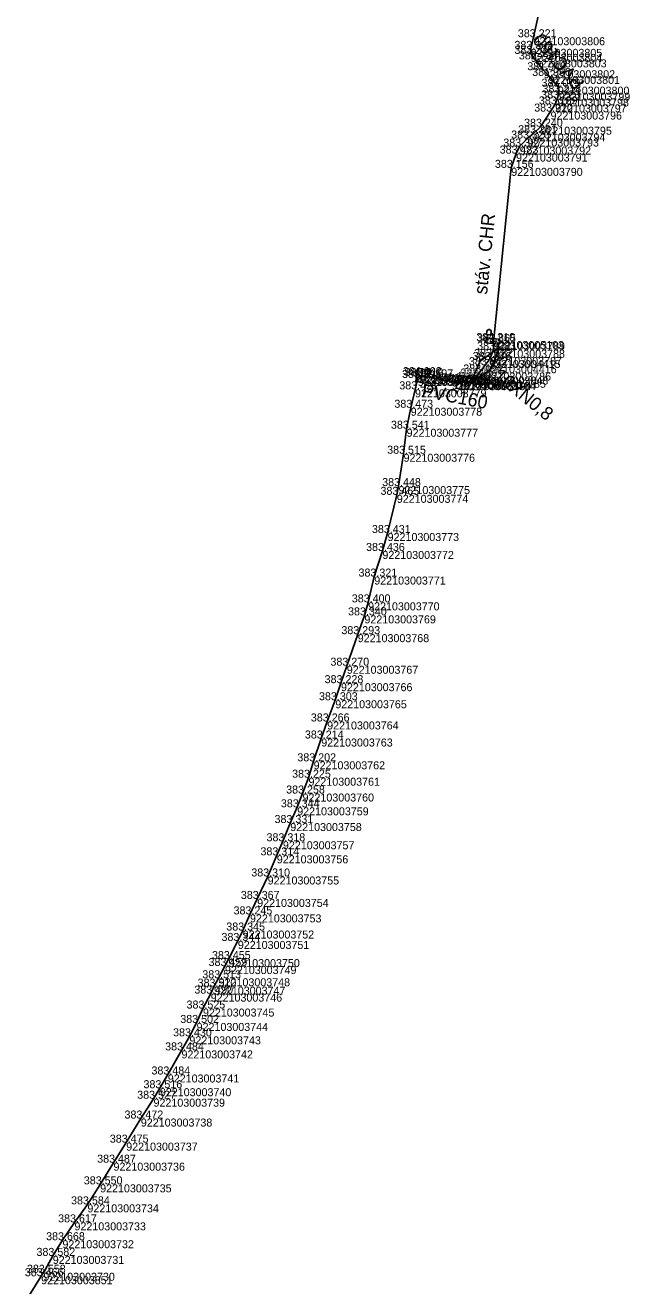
# Model space of a CAD drawing. Extents: x -771047 to -756200, y -1053876 to -1046520.
# Drawn here: x -756827.8 to -756737.2, y -1047067 to -1046877.9 of the extents above; entities that cross this region are included whole.
import ezdxf

# ---------------------------------------------------------------- set-up
doc = ezdxf.new("R2010")
doc.units = 0
for name, color, linetype in [('Vrstva 32', 7, 'Continuous'), ('Vrstva 33', 7, 'Continuous'), ('Vrstva 60', 7, 'Continuous'), ('Vrstva 61', 7, 'Continuous')]:
    doc.layers.add(name, color=color, linetype=linetype)

msp = doc.modelspace()

# ---------------------------------------------------------------- linework, layer by layer
at = {"layer": 'Vrstva 32'}
for points in [[(-756751.57, -1046879.71), (-756750.8, -1046876.1)], [(-756748.33, -1046889.77), (-756747.99, -1046888.89), (-756747.79, -1046888.02), (-756747.92, -1046887.12), (-756749.33, -1046885.51), (-756750.06, -1046884.66), (-756751.33, -1046883.03), (-756751.99, -1046882.2), (-756751.99, -1046881.45), (-756751.57, -1046879.71)], [(-756753.66, -1046896.11), (-756752.48, -1046894.9), (-756751.52, -1046894.11), (-756750.55, -1046893.13), (-756749.03, -1046890.86), (-756748.33, -1046889.77)], [(-756768.46, -1046930.51), (-756766.97, -1046930.72), (-756763.83, -1046931.32), (-756761.94, -1046931.43), (-756760.44, -1046931.08), (-756760.08, -1046930.6), (-756759.66, -1046929.99), (-756758.82, -1046928.9), (-756758.24, -1046928.11), (-756758.03, -1046927.68), (-756757.58, -1046926.58), (-756757.57, -1046925.42), (-756754.92, -1046899.3), (-756754.2, -1046897.16), (-756753.66, -1046896.11)], [(-756761.04, -1046931.61), (-756759.6, -1046928.27), (-756756.61, -1046926.19), (-756758.05, -1046929.53), (-756761.04, -1046931.61)], [(-756768.46, -1046930.51), (-756768.93, -1046930.81), (-756769.34, -1046932.52), (-756769.99, -1046935.28), (-756770.6, -1046938.43), (-756771.06, -1046942.18), (-756771.81, -1046947.03), (-756772.07, -1046948.34), (-756773.45, -1046954.07), (-756774.23, -1046956.76), (-756775.45, -1046960.6), (-756776.37, -1046964.47), (-756776.93, -1046966.42), (-756777.93, -1046969.24), (-756779.57, -1046973.97), (-756780.44, -1046976.59), (-756781.29, -1046979.15), (-756782.51, -1046982.33), (-756783.4, -1046984.89), (-756784.54, -1046988.31), (-756785.31, -1046990.77), (-756786.2, -1046993.14), (-756787, -1046995.21), (-756788.04, -1046997.57), (-756789.14, -1047000.3), (-756790.06, -1047002.41), (-756791.43, -1047005.58), (-756793, -1047008.95), (-756794.08, -1047011.27), (-756795.17, -1047013.69), (-756795.9, -1047015.25), (-756797.32, -1047017.97), (-756797.83, -1047019.02), (-756798.78, -1047020.85), (-756799.48, -1047022.11), (-756799.97, -1047023.15), (-756801.13, -1047025.39), (-756802.08, -1047027.55), (-756803.16, -1047029.56), (-756804.35, -1047031.67), (-756806.4, -1047035.28), (-756807.59, -1047037.34), (-756808.54, -1047038.92), (-756810.44, -1047041.89), (-756812.63, -1047045.5), (-756814.54, -1047048.51), (-756816.54, -1047051.76), (-756818.45, -1047054.76), (-756820.39, -1047057.46), (-756822.19, -1047060.14), (-756823.64, -1047062.49), (-756825.05, -1047065.02), (-756825.38, -1047065.54), (-756827.16, -1047068.41)]]:
    msp.add_lwpolyline(points, dxfattribs=at)
at = {"layer": 'Vrstva 33'}
for points in [[(-756748.33, -1046889.77), (-756747.99, -1046888.89), (-756747.79, -1046888.02), (-756747.92, -1046887.12), (-756749.33, -1046885.51), (-756750.06, -1046884.66), (-756751.33, -1046883.03), (-756751.99, -1046882.2), (-756751.99, -1046881.45), (-756751.57, -1046879.71)], [(-756757.57, -1046925.42), (-756754.92, -1046899.3), (-756754.2, -1046897.16), (-756753.66, -1046896.11)], [(-756758.62, -1046924.29), (-756758.56, -1046923.77)], [(-756757.37, -1046924.41), (-756758.62, -1046924.29)], [(-756758.56, -1046923.77), (-756758.5, -1046923.62), (-756758.28, -1046923.53), (-756758.17, -1046923.54), (-756757.98, -1046923.67), (-756757.95, -1046923.83)], [(-756757.95, -1046923.83), (-756758, -1046924.35)], [(-756767.85, -1046930.75), (-756767.68, -1046929.51)], [(-756767.68, -1046929.51), (-756767.16, -1046929.59)], [(-756767.16, -1046929.59), (-756767.01, -1046929.66), (-756766.93, -1046929.88), (-756766.95, -1046929.99), (-756767.08, -1046930.18), (-756767.25, -1046930.2)], [(-756768.46, -1046930.51), (-756766.97, -1046930.72), (-756763.83, -1046931.32), (-756761.94, -1046931.43), (-756760.44, -1046931.08)], [(-756767.25, -1046930.2), (-756767.76, -1046930.12)], [(-756761.79, -1046931.85), (-756761.55, -1046930.61)], [(-756761.16, -1046931.32), (-756761.67, -1046931.22)], [(-756761.55, -1046930.61), (-756761.04, -1046930.71)], [(-756761.04, -1046930.71), (-756760.89, -1046930.79), (-756760.82, -1046931.01), (-756760.84, -1046931.12), (-756760.99, -1046931.31), (-756761.16, -1046931.32)]]:
    msp.add_lwpolyline(points, dxfattribs=at)
for points in [[(-756758.74, -1046925.55), (-756758.66, -1046924.81), (-756756.66, -1046925.01), (-756756.74, -1046925.75)], [(-756768.93, -1046929.34), (-756768.19, -1046929.44), (-756768.48, -1046931.44), (-756769.21, -1046931.33)], [(-756762.8, -1046930.38), (-756762.06, -1046930.52), (-756762.44, -1046932.5), (-756763.18, -1046932.36)]]:
    msp.add_lwpolyline(points, close=True, dxfattribs=at)
at = {"layer": 'Vrstva 60'}
for p, q in [((-756751.57, -1046879.71), (-756751.57, -1046879.71)), ((-756751.99, -1046881.45), (-756751.99, -1046881.45)), ((-756751.99, -1046882.2), (-756751.99, -1046882.2)), ((-756751.33, -1046883.03), (-756751.33, -1046883.03)), ((-756750.06, -1046884.66), (-756750.06, -1046884.66)), ((-756749.33, -1046885.51), (-756749.33, -1046885.51)), ((-756747.92, -1046887.12), (-756747.92, -1046887.12)), ((-756747.79, -1046888.02), (-756747.79, -1046888.02)), ((-756748.33, -1046889.77), (-756748.33, -1046889.77)), ((-756747.99, -1046888.89), (-756747.99, -1046888.89)), ((-756749.03, -1046890.86), (-756749.03, -1046890.86)), ((-756750.55, -1046893.13), (-756750.55, -1046893.13)), ((-756752.48, -1046894.9), (-756752.48, -1046894.9)), ((-756751.52, -1046894.11), (-756751.52, -1046894.11)), ((-756754.2, -1046897.16), (-756754.2, -1046897.16)), ((-756753.66, -1046896.11), (-756753.66, -1046896.11)), ((-756754.92, -1046899.3), (-756754.92, -1046899.3)), ((-756757.7, -1046925.28), (-756757.7, -1046925.28)), ((-756757.57, -1046925.42), (-756757.57, -1046925.42)), ((-756758.24, -1046928.11), (-756758.24, -1046928.11)), ((-756758.03, -1046927.68), (-756758.03, -1046927.68)), ((-756757.58, -1046926.58), (-756757.58, -1046926.58)), ((-756759.66, -1046929.99), (-756759.66, -1046929.99)), ((-756758.82, -1046928.9), (-756758.82, -1046928.9)), ((-756768.93, -1046930.81), (-756768.93, -1046930.81)), ((-756768.7, -1046930.39), (-756768.7, -1046930.39)), ((-756768.46, -1046930.51), (-756768.46, -1046930.51)), ((-756766.97, -1046930.72), (-756766.97, -1046930.72)), ((-756763.83, -1046931.32), (-756763.83, -1046931.32)), ((-756762.62, -1046931.44), (-756762.62, -1046931.44)), ((-756761.94, -1046931.43), (-756761.94, -1046931.43)), ((-756760.44, -1046931.08), (-756760.44, -1046931.08)), ((-756760.08, -1046930.6), (-756760.08, -1046930.6)), ((-756769.34, -1046932.52), (-756769.34, -1046932.52)), ((-756769.99, -1046935.28), (-756769.99, -1046935.28)), ((-756770.6, -1046938.43), (-756770.6, -1046938.43)), ((-756771.06, -1046942.18), (-756771.06, -1046942.18)), ((-756771.81, -1046947.03), (-756771.81, -1046947.03)), ((-756772.07, -1046948.34), (-756772.07, -1046948.34)), ((-756773.45, -1046954.07), (-756773.45, -1046954.07)), ((-756774.23, -1046956.76), (-756774.23, -1046956.76)), ((-756775.45, -1046960.6), (-756775.45, -1046960.6)), ((-756776.37, -1046964.47), (-756776.37, -1046964.47)), ((-756776.93, -1046966.42), (-756776.93, -1046966.42)), ((-756777.93, -1046969.24), (-756777.93, -1046969.24)), ((-756779.57, -1046973.97), (-756779.57, -1046973.97)), ((-756780.44, -1046976.59), (-756780.44, -1046976.59)), ((-756781.29, -1046979.15), (-756781.29, -1046979.15)), ((-756782.51, -1046982.33), (-756782.51, -1046982.33)), ((-756783.4, -1046984.89), (-756783.4, -1046984.89)), ((-756784.54, -1046988.31), (-756784.54, -1046988.31)), ((-756785.31, -1046990.77), (-756785.31, -1046990.77)), ((-756786.2, -1046993.14), (-756786.2, -1046993.14)), ((-756787, -1046995.21), (-756787, -1046995.21)), ((-756788.04, -1046997.57), (-756788.04, -1046997.57)), ((-756789.14, -1047000.3), (-756789.14, -1047000.3)), ((-756790.06, -1047002.41), (-756790.06, -1047002.41)), ((-756791.43, -1047005.58), (-756791.43, -1047005.58)), ((-756793, -1047008.95), (-756793, -1047008.95)), ((-756794.08, -1047011.27), (-756794.08, -1047011.27)), ((-756795.17, -1047013.69), (-756795.17, -1047013.69)), ((-756795.9, -1047015.25), (-756795.9, -1047015.25)), ((-756797.32, -1047017.97), (-756797.32, -1047017.97)), ((-756797.83, -1047019.02), (-756797.83, -1047019.02)), ((-756799.48, -1047022.11), (-756799.48, -1047022.11)), ((-756798.78, -1047020.85), (-756798.78, -1047020.85)), ((-756799.97, -1047023.15), (-756799.97, -1047023.15)), ((-756801.13, -1047025.39), (-756801.13, -1047025.39)), ((-756802.08, -1047027.55), (-756802.08, -1047027.55)), ((-756803.16, -1047029.56), (-756803.16, -1047029.56)), ((-756804.35, -1047031.67), (-756804.35, -1047031.67)), ((-756806.4, -1047035.28), (-756806.4, -1047035.28)), ((-756807.59, -1047037.34), (-756807.59, -1047037.34)), ((-756808.54, -1047038.92), (-756808.54, -1047038.92)), ((-756810.44, -1047041.89), (-756810.44, -1047041.89)), ((-756812.63, -1047045.5), (-756812.63, -1047045.5)), ((-756814.54, -1047048.51), (-756814.54, -1047048.51)), ((-756816.54, -1047051.76), (-756816.54, -1047051.76)), ((-756818.45, -1047054.76), (-756818.45, -1047054.76)), ((-756820.39, -1047057.46), (-756820.39, -1047057.46)), ((-756822.19, -1047060.14), (-756822.19, -1047060.14)), ((-756823.64, -1047062.49), (-756823.64, -1047062.49)), ((-756825.38, -1047065.54), (-756825.38, -1047065.54)), ((-756825.05, -1047065.02), (-756825.05, -1047065.02))]:
    msp.add_line(p, q, dxfattribs=at)

# ---------------------------------------------------------------- texts
at = {"layer": 'Vrstva 32'}
msp.add_text('10XN0,8', height=2, rotation=320.7695, dxfattribs=at).set_placement((-756757.7, -1046930.76))
at = {"layer": 'Vrstva 33'}
for s, rotation, p in [('PVC160', 130.5566, (-756743.83, -1046886.48)), ('stáv. CHR', 84.1911, (-756758.55, -1046918.35)), ('PVC160', 349.1571, (-756768.45, -1046933.61))]:
    msp.add_text(s, height=2, rotation=rotation, dxfattribs=at).set_placement(p)
at = {"layer": 'Vrstva 60'}
for s, p in [('922103003806', (-756751.57, -1046880.91)), ('922103003804', (-756751.99, -1046883.4)), ('922103003805', (-756751.99, -1046882.65)), ('922103003803', (-756751.33, -1046884.23)), ('922103003802', (-756750.06, -1046885.86)), ('922103003801', (-756749.33, -1046886.71)), ('922103003800', (-756747.92, -1046888.32)), ('922103003799', (-756747.79, -1046889.22)), ('922103003797', (-756748.33, -1046890.97)), ('922103003798', (-756747.99, -1046890.09)), ('922103003796', (-756749.03, -1046892.06)), ('922103003794', (-756751.52, -1046895.31)), ('922103003795', (-756750.55, -1046894.33)), ('922103003793', (-756752.48, -1046896.1)), ('922103003791', (-756754.2, -1046898.36)), ('922103003792', (-756753.66, -1046897.31)), ('922103003790', (-756754.92, -1046900.5)), ('922103005103', (-756757.7, -1046926.48)), ('922103003789', (-756757.57, -1046926.62)), ('922103004415', (-756758.24, -1046929.31)), ('922103003787', (-756758.03, -1046928.88)), ('922103003788', (-756757.58, -1046927.78)), ('922103003786', (-756759.66, -1046931.2)), ('922103004416', (-756758.82, -1046930.1)), ('922103003780', (-756768.93, -1046932.01)), ('922103005066', (-756768.7, -1046931.59)), ('922103003781', (-756768.46, -1046931.71)), ('922103003782', (-756766.97, -1046931.92)), ('922103003783', (-756763.83, -1046932.52)), ('922103005104', (-756762.62, -1046932.64)), ('922103003784', (-756761.94, -1046932.63)), ('922103003785', (-756760.44, -1046932.28)), ('922103003848', (-756760.08, -1046931.8)), ('922103003779', (-756769.34, -1046933.72)), ('922103003778', (-756769.99, -1046936.48)), ('922103003777', (-756770.6, -1046939.63)), ('922103003776', (-756771.06, -1046943.38)), ('922103003775', (-756771.81, -1046948.23)), ('922103003774', (-756772.07, -1046949.54)), ('922103003773', (-756773.45, -1046955.27)), ('922103003772', (-756774.23, -1046957.96)), ('922103003771', (-756775.45, -1046961.8)), ('922103003770', (-756776.37, -1046965.67)), ('922103003769', (-756776.93, -1046967.62)), ('922103003768', (-756777.93, -1046970.44)), ('922103003767', (-756779.57, -1046975.18)), ('922103003766', (-756780.44, -1046977.79)), ('922103003765', (-756781.29, -1046980.35)), ('922103003764', (-756782.51, -1046983.53)), ('922103003763', (-756783.4, -1046986.09)), ('922103003762', (-756784.54, -1046989.51)), ('922103003761', (-756785.31, -1046991.97)), ('922103003760', (-756786.2, -1046994.34)), ('922103003759', (-756787, -1046996.41)), ('922103003758', (-756788.04, -1046998.77)), ('922103003757', (-756789.14, -1047001.5)), ('922103003756', (-756790.06, -1047003.61)), ('922103003755', (-756791.43, -1047006.78)), ('922103003754', (-756793, -1047010.15)), ('922103003753', (-756794.08, -1047012.47)), ('922103003752', (-756795.17, -1047014.89)), ('922103003751', (-756795.9, -1047016.45)), ('922103003750', (-756797.32, -1047019.17)), ('922103003749', (-756797.83, -1047020.22)), ('922103003747', (-756799.48, -1047023.31)), ('922103003748', (-756798.78, -1047022.05)), ('922103003746', (-756799.97, -1047024.35)), ('922103003745', (-756801.13, -1047026.59)), ('922103003744', (-756802.08, -1047028.75)), ('922103003743', (-756803.16, -1047030.76)), ('922103003742', (-756804.35, -1047032.87)), ('922103003741', (-756806.4, -1047036.48)), ('922103003740', (-756807.59, -1047038.54)), ('922103003739', (-756808.54, -1047040.11)), ('922103003738', (-756810.44, -1047043.09)), ('922103003737', (-756812.63, -1047046.7)), ('922103003736', (-756814.54, -1047049.71)), ('922103003735', (-756816.54, -1047052.96)), ('922103003734', (-756818.45, -1047055.96)), ('922103003733', (-756820.39, -1047058.66)), ('922103003732', (-756822.19, -1047061.34)), ('922103003731', (-756823.64, -1047063.69)), ('922103003851', (-756825.38, -1047066.74)), ('922103003730', (-756825.05, -1047066.22))]:
    msp.add_text(s, height=1.2, dxfattribs=at).set_placement(p)
at = {"layer": 'Vrstva 61'}
for s, p in [('383.221', (-756753.93, -1046879.71)), ('383.305', (-756754.44, -1046881.45)), ('383.233', (-756754.45, -1046882.2)), ('382.733', (-756753.78, -1046883.03)), ('381.948', (-756752.51, -1046884.66)), ('381.950', (-756751.78, -1046885.51)), ('383.079', (-756750.38, -1046887.12)), ('383.223', (-756750.44, -1046888.89)), ('383.218', (-756750.24, -1046888.02)), ('383.210', (-756751.48, -1046890.86)), ('383.189', (-756750.78, -1046889.77)), ('383.240', (-756753, -1046893.13)), ('383.320', (-756754.93, -1046894.9)), ('383.281', (-756753.88, -1046894.11)), ('383.483', (-756756.65, -1046897.16)), ('383.387', (-756756.11, -1046896.11)), ('383.156', (-756757.37, -1046899.3)), ('384.210', (-756760.15, -1046925.28)), ('382.865', (-756760.03, -1046925.42)), ('383.083', (-756760.03, -1046926.58)), ('383.642', (-756761.27, -1046928.9)), ('383.576', (-756760.7, -1046928.11)), ('383.582', (-756760.48, -1046927.68)), ('383.391', (-756771.29, -1046930.81)), ('384.092', (-756771.15, -1046930.39)), ('383.319', (-756770.92, -1046930.51)), ('382.597', (-756769.42, -1046930.72)), ('383.423', (-756762.89, -1046931.08)), ('383.557', (-756762.53, -1046930.6)), ('383.434', (-756762.11, -1046929.99)), ('383.421', (-756771.7, -1046932.52)), ('382.538', (-756766.28, -1046931.32)), ('383.850', (-756765.07, -1046931.44)), ('382.604', (-756764.39, -1046931.43)), ('383.473', (-756772.44, -1046935.28)), ('383.541', (-756772.95, -1046938.43)), ('383.515', (-756773.52, -1046942.18)), ('383.448', (-756774.27, -1046947.03)), ('383.465', (-756774.52, -1046948.34)), ('383.431', (-756775.8, -1046954.07)), ('383.436', (-756776.68, -1046956.76)), ('383.321', (-756777.81, -1046960.6)), ('383.400', (-756778.82, -1046964.47)), ('383.340', (-756779.38, -1046966.42)), ('383.293', (-756780.38, -1046969.24)), ('383.270', (-756782.02, -1046973.97)), ('383.228', (-756782.89, -1046976.59)), ('383.303', (-756783.74, -1046979.15)), ('383.266', (-756784.96, -1046982.33)), ('383.214', (-756785.85, -1046984.89)), ('383.202', (-756786.98, -1046988.31)), ('383.225', (-756787.77, -1046990.77)), ('383.258', (-756788.66, -1046993.14)), ('383.344', (-756789.45, -1046995.21)), ('383.331', (-756790.4, -1046997.57)), ('383.318', (-756791.6, -1047000.3)), ('383.314', (-756792.51, -1047002.41)), ('383.310', (-756793.88, -1047005.58)), ('383.367', (-756795.45, -1047008.95)), ('383.245', (-756796.54, -1047011.27)), ('383.345', (-756797.63, -1047013.69)), ('383.344', (-756798.35, -1047015.25)), ('383.455', (-756799.78, -1047017.97)), ('383.459', (-756800.29, -1047019.02)), ('383.513', (-756801.23, -1047020.85)), ('383.490', (-756802.42, -1047023.15)), ('383.510', (-756801.93, -1047022.11)), ('383.525', (-756803.59, -1047025.39)), ('383.502', (-756804.53, -1047027.55)), ('383.430', (-756805.61, -1047029.56)), ('383.484', (-756806.8, -1047031.67)), ('383.484', (-756808.85, -1047035.28)), ('383.527', (-756810.99, -1047038.92)), ('383.516', (-756810.04, -1047037.34)), ('383.472', (-756812.89, -1047041.89)), ('383.475', (-756815.09, -1047045.5)), ('383.487', (-756816.99, -1047048.51)), ('383.550', (-756818.99, -1047051.76)), ('383.584', (-756820.9, -1047054.76)), ('383.617', (-756822.84, -1047057.46)), ('383.668', (-756824.64, -1047060.14)), ('383.582', (-756826.08, -1047062.49)), ('383.558', (-756827.51, -1047065.02)), ('383.466', (-756827.83, -1047065.54))]:
    msp.add_text(s, height=1.2, dxfattribs=at).set_placement(p)

doc.saveas('drawing.dxf')
